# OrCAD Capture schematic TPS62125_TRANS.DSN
size D
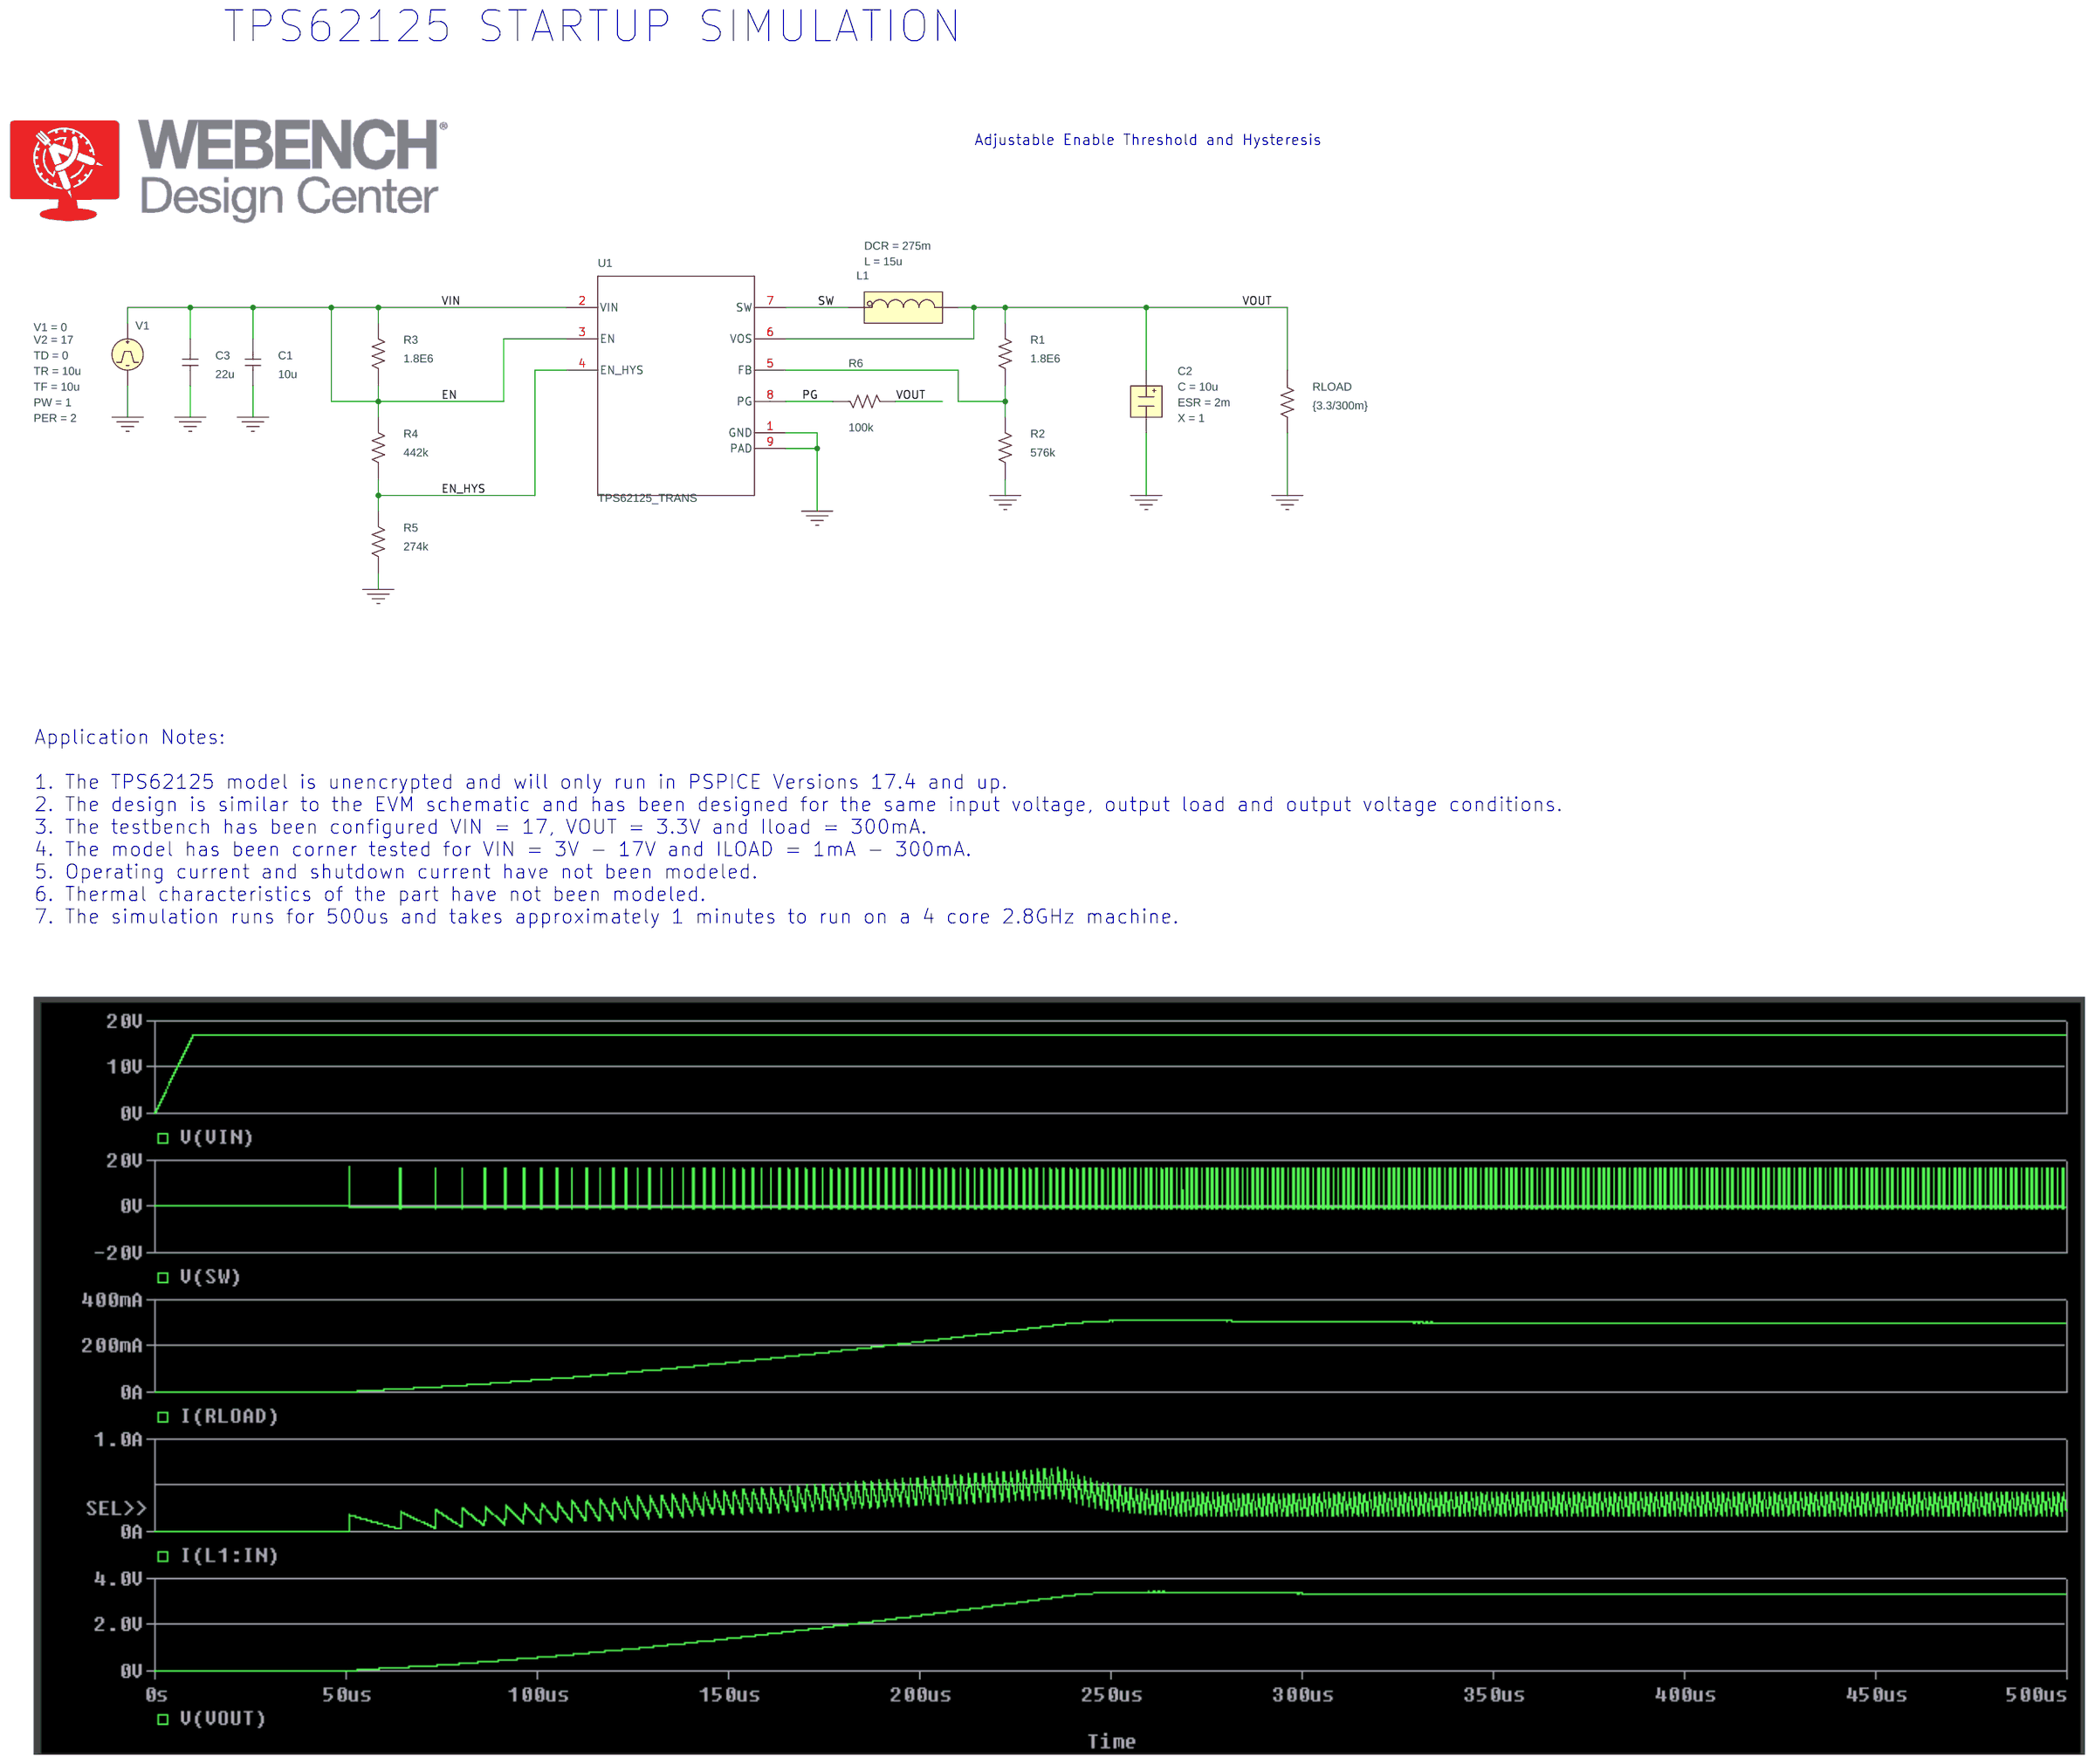
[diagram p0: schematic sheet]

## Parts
C1  10u  [RAD/CK05]
C2  CESR
C3  22u  [RAD/CK05]
L1  LDCR
R1  1.8E6  [AX/RC05]
R2  576k  [AX/RC05]
R3  1.8E6  [AX/RC05]
R4  442k  [AX/RC05]
R5  274k  [AX/RC05]
R6  100k  [AX/RC05]
RLOAD  {3.3/300m}  [AX/RC05]
U1  TPS62125_TRANS  [DSG0008A]
V1  VPULSE

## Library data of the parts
C1 C3 = C
C2 = CESR: C: 10u; ESR: 2m; IC: 0; PSpiceTemplate: X^@REFDES %IN %OUT @MODEL PARAMS:  ?C|C=@C||C=100u|  ?ESR|ESR=@ESR||ESR=0.01| ?X|X=@X||X=2|  ?IC|IC=@IC||IC=2|; X: 1
L1 = LDCR: DCR: 275m; IC: 0; L: 15u; PSpiceTemplate: X^@REFDES %IN %OUT @MODEL PARAMS:  ?L|L=@L||L=1u|  ?DCR|DCR=@DCR||DCR=0.01| ?IC|IC=@IC||IC=0|
R1-R6 RLOAD = R
U1 = TPS62125_TRANS: < Value >: TPS62125; PartNumber: TPS62125
V1 = VPULSE: PER: 2; PW: 1; TD: 0; TF: 10u; TR: 10u; V1: 0; V2: 17

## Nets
0: C1.1 C2.3(OUT) C3.1 R2.1 R5.1 RLOAD.2 U1.1(GND) U1.9(PAD) V1.2(-)
EN: C1.2 C3.2 R3.1 R3.2 R4.2 U1.2(VIN) U1.3(EN) V1.1(+)
EN_HYS: R4.1 R5.2 U1.4(EN_HYS)
PG: R6.1 U1.8(PG)
SW: L1.1(IN) U1.7(SW)
VOUT: C2.1(IN) L1.3(OUT) R1.2 R6.2 RLOAD.1 U1.6(VOS)
N16309740: R1.1 R2.2 U1.5(FB)

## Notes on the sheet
- TPS62125 STARTUP SIMULATION
- Adjustable Enable Threshold and Hysteresis
- Application Notes:
  1. The TPS62125 model is unencrypted and will only run in PSPICE Versions 17.4 and up.
  2. The design is similar to the EVM schematic and has been designed for the same input voltage, output load and output voltage conditions.
  3. The testbench has been configured VIN = 17, VOUT = 3.3V and Iload = 300mA.
  4. The model has been corner tested for VIN = 3V - 17V and ILOAD = 1mA - 300mA.
  5. Operating current and shutdown current have not been modeled.
  6. Thermal characteristics of the part have not been modeled.
  7. The simulation runs for 500us and takes approximately 1 minutes to run on a 4 core 2.8GHz machine.
